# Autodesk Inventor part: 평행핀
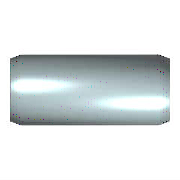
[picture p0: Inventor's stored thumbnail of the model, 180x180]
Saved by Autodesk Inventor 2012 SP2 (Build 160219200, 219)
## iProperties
IsCustomPart: 0
Created: 2009-02
Part Number: 평행핀
Material: 강, 연강
Description: 평행 핀
Document SubType Name: Modeling
Standard: KS B 1320
Designer: KYOUNG IL JANG
Standards Organization: KS
Language: ko-KR
Size Designation: B 5 x  20
Categories: <MemberInstance><Categories><Category DisplayName="조임쇠" InternalName="e4da775c-781d-43d5-af7c-5136215cf5a6" Mnemonic="FSTN"><Category DisplayName="핀" InternalNa
Density: 1 g/cm^3
Author: KYOUNG IL JANG
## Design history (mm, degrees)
sketch "스케치"
  geometry: C1 r 2.5 at (0, 0); 1 further point
  constraints: 1 centre point, 1 coincident
  dimensions: "d1" = 5 diameter of C1 (= NND)
extrude "본체" new body sketch "스케치" distance "d2" = 20 (= NLG); taper "d3" = 0 deg
chamfer "스케치2" distance "d8" = 0.8 (= PHH); stored, may be unused: angle "d9" = 15 deg (= FAWI), second distance "d12" = 0.8 (= PHH)
body "Solid1"
chamfer "모따기1" distance "d4" = 0.8 (= PHH); stored, may be unused: angle "d5" = 15 deg (= FAWI), second distance "d11" = 0.8 (= PHH)
other parameters: "NND" = 5 [user parameter; used in 1 equation term], "NLG" = 20 [user parameter; used in 1 equation term], "PHH" = 0.8 [user parameter; used in 4 equation terms], "FAWI" = 15 deg [user parameter; used in 2 equation terms], "d13" = 0, "d15" = 0, "d16" = 0, "KAH" = 0.63 [user parameter]
